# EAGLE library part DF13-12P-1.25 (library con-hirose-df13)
DF13-12P 1.25mm Pitch Miniature Crimping Connector.
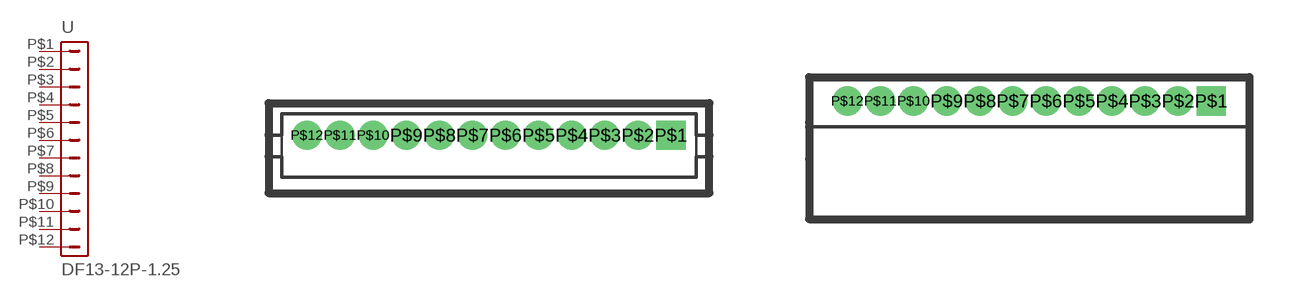
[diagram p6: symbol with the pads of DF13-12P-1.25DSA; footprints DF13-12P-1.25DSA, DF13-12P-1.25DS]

Designator prefix -

## DF13-12P-1.25DSA  [DF13-12P-1.25DSA]
P$1  1  pas
P$2  2  pas
P$3  3  pas
P$4  4  pas
P$5  5  pas
P$6  6  pas
P$7  7  pas
P$8  8  pas
P$9  9  pas
P$10  10  pas
P$11  11  pas
P$12  12  pas

## DF13-12P-1.25DS  [DF13-12P-1.25DS]
Pads as for DF13-12P-1.25DSA

## DF13-12P-1.25V  [DF13C-12P-1.25V]
Pads as for DF13-12P-1.25DSA

## DF13-12P-1.25H  [DF13A-12P-1.25H]
Pads as for DF13-12P-1.25DSA

## Footprint DF13-12P-1.25DSA (pad centres in mm)
Single Row Straight Pin Header (Through hole)
drill 0.6 pad 1.016 square: P$1 6.875,0
drill 0.6 pad 1.016 round: P$2 5.625,0; P$3 4.375,0; P$4 3.125,0; P$5 1.875,0; P$6 0.625,0; P$7 -0.625,0; P$8 -1.875,0; P$9 -3.125,0; P$10 -4.375,0; P$11 -5.625,0; P$12 -6.875,0

## Footprint DF13-12P-1.25DS (pad centres in mm)
Single Row Right Angle Pin Header (Through hole)
drill 0.6 pad 1.016 square: P$1 6.875,0
drill 0.6 pad 1.016 round: P$2 5.625,0; P$3 4.375,0; P$4 3.125,0; P$5 1.875,0; P$6 0.625,0; P$7 -0.625,0; P$8 -1.875,0; P$9 -3.125,0; P$10 -4.375,0; P$11 -5.625,0; P$12 -6.875,0

## Footprint DF13C-12P-1.25V (pad centres in mm)
Single Row Straight Pin Header (SMT)
smd 1.6 x 2.2: M$0 9.325,-1.8; M$1 -9.325,-1.8
smd 0.7 x 1.8: P$1 -6.875,0.9; P$2 -5.625,0.9; P$3 -4.375,0.9; P$4 -3.125,0.9; P$5 -1.875,0.9; P$6 -0.625,0.9; P$7 0.625,0.9; P$8 1.875,0.9; P$9 3.125,0.9; P$10 4.375,0.9; P$11 5.625,0.9; P$12 6.875,0.9

## Footprint DF13A-12P-1.25H (pad centres in mm)
Single Row Straight Pin Header (SMT)
smd 1.6 x 2.2: M$0 -9.225,2.4; M$1 9.225,2.4
smd 0.7 x 1.8: P$1 -6.875,-0.9; P$2 -5.625,-0.9; P$3 -4.375,-0.9; P$4 -3.125,-0.9; P$5 -1.875,-0.9; P$6 -0.625,-0.9; P$7 0.625,-0.9; P$8 1.875,-0.9; P$9 3.125,-0.9; P$10 4.375,-0.9; P$11 5.625,-0.9; P$12 6.875,-0.9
